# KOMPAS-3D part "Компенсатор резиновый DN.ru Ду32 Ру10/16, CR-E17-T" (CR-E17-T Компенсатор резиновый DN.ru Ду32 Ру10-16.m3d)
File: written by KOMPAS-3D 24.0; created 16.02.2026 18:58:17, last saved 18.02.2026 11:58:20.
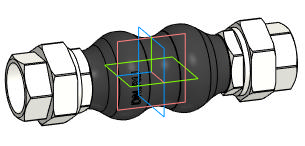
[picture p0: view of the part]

Document properties: Автор: DN.RU; Полное имя файла: CR-E17-T Компенсатор резиновый DN.ru Ду32 Ру10-16.cdw

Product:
- Body: Твердое тело1  | qty 1
    Масса: 1.835825
- Part/product: Компенсатор резиновый DN.ru Ду32 Ру10/16  | designation CR-E17-T
    Масса: 1.46
    Раздел спецификации: Прочие изделия
    Форматы листов документа: A3
    Комментарий: D140-02212
    Примечание: D140-02212
    additional columns: Типовые

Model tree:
1. Твердое тело1  (labels: Твердое тело1)

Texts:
  CR-E17-T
